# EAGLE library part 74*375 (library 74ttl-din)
4-bit bistable LATCH
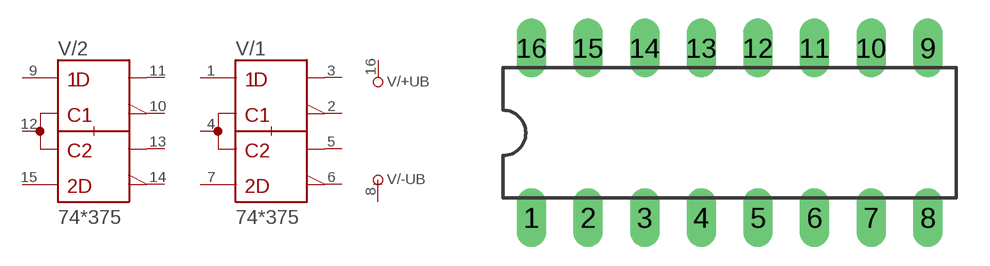
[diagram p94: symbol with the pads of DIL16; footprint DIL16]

Designator prefix V; gates /+UB=+UB /-UB=-UB /1=375 /2=375

## 74375N  [DIL16]
1  /1:1D  in
2  /1:1Q\  out
3  /1:1Q  out
4  /1:1C,2C  in
5  /1:2Q  out
6  /1:2Q\  out
7  /1:2D  in
8  /-UB:-UB  pwr
9  /2:1D  in
10  /2:1Q\  out
11  /2:1Q  out
12  /2:1C,2C  in
13  /2:2Q  out
14  /2:2Q\  out
15  /2:2D  in
16  /+UB:+UB  pwr

## Footprint DIL16 (pad centres in mm)
Dual In Line Package
drill 0.813 long: 1 -8.89,-3.81; 2 -6.35,-3.81; 3 -3.81,-3.81; 4 -1.27,-3.81; 5 1.27,-3.81; 6 3.81,-3.81; 7 6.35,-3.81; 8 8.89,-3.81; 9 8.89,3.81; 10 6.35,3.81; 11 3.81,3.81; 12 1.27,3.81; 13 -1.27,3.81; 14 -3.81,3.81; 15 -6.35,3.81; 16 -8.89,3.81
